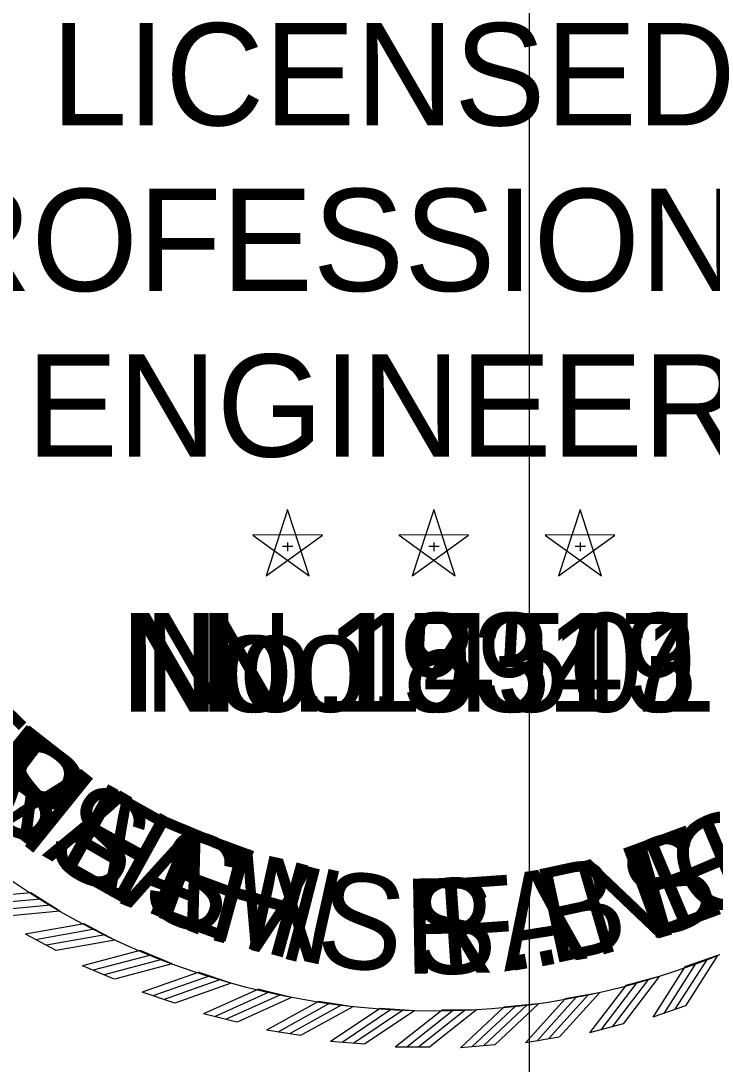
# Model space of a CAD drawing. Extents: x 18 to 14744716, y -5 to 1829144.
# Drawn here: x 17.7213 to 17.7969, y 10.8183 to 10.9324 of the extents above; entities that cross this region are included whole.
import ezdxf

# ---------------------------------------------------------------- set-up
doc = ezdxf.new("R2010")
doc.units = 0
for name, color, linetype in [('B_StampHSS', 7, 'Continuous'), ('B_StampJSB', 7, 'Continuous'), ('B_StampSCR', 7, 'Continuous'), ('B_StampSFH', 7, 'Continuous'), ('R_No Plot', 7, 'Continuous')]:
    doc.layers.add(name, color=color, linetype=linetype)

msp = doc.modelspace()

# ---------------------------------------------------------------- linework, layer by layer
at = {"layer": 'B_StampHSS'}
for p, q in [((17.75045, 10.87892), (17.74809, 10.87168)), ((17.7528, 10.87168), (17.75045, 10.87893)), ((17.76644, 10.87892), (17.76408, 10.87168)), ((17.76879, 10.87168), (17.76644, 10.87893)), ((17.78243, 10.87892), (17.78007, 10.87168)), ((17.78478, 10.87168), (17.78243, 10.87893)), ((17.75425, 10.87615), (17.74664, 10.87616)), ((17.74664, 10.87615), (17.7528, 10.87168)), ((17.7481, 10.87168), (17.75426, 10.87615)), ((17.75045, 10.87534), (17.75045, 10.87439)), ((17.77024, 10.87615), (17.76263, 10.87616)), ((17.76264, 10.87615), (17.76879, 10.87168)), ((17.76409, 10.87168), (17.77025, 10.87615)), ((17.76645, 10.87534), (17.76645, 10.87439)), ((17.78623, 10.87615), (17.77862, 10.87616)), ((17.77863, 10.87615), (17.78478, 10.87168)), ((17.78008, 10.87168), (17.78624, 10.87615)), ((17.78244, 10.87534), (17.78244, 10.87439)), ((17.7499, 10.87494), (17.75104, 10.87494)), ((17.7659, 10.87494), (17.76703, 10.87494)), ((17.78189, 10.87494), (17.78302, 10.87494)), ((17.72555, 10.83498), (17.72236, 10.83702)), ((17.73156, 10.83184), (17.72822, 10.83361)), ((17.72514, 10.8307), (17.7218, 10.83247)), ((17.73781, 10.82922), (17.73434, 10.8307)), ((17.79746, 10.83015), (17.7939, 10.82889)), ((17.7315, 10.82755), (17.72804, 10.82903)), ((17.74426, 10.82711), (17.74068, 10.82831)), ((17.79108, 10.82784), (17.78743, 10.82688)), ((17.73811, 10.82493), (17.73453, 10.82613)), ((17.75086, 10.82555), (17.74719, 10.82645)), ((17.78453, 10.82608), (17.78081, 10.82542)), ((17.75757, 10.82454), (17.75383, 10.82513)), ((17.77786, 10.82486), (17.7741, 10.82451)), ((17.74491, 10.82287), (17.74125, 10.82376)), ((17.76433, 10.82409), (17.76056, 10.82436)), ((17.77111, 10.82419), (17.76734, 10.82416)), ((17.79395, 10.82465), (17.79039, 10.82339)), ((17.78713, 10.82266), (17.78348, 10.8217)), ((17.75186, 10.82138), (17.74814, 10.82196)), ((17.75891, 10.82046), (17.75515, 10.82074)), ((17.77311, 10.82039), (17.76935, 10.82004)), ((17.78016, 10.82123), (17.77645, 10.82058)), ((17.76601, 10.82013), (17.76224, 10.8201))]:
    msp.add_line(p, q, dxfattribs=at)
for points in [[(17.72237, 10.83701), (17.71587, 10.83641)], [(17.72342, 10.83632), (17.71692, 10.83572)], [(17.72454, 10.83564), (17.71804, 10.83504)], [(17.72555, 10.83498), (17.71906, 10.83437)], [(17.72822, 10.83361), (17.7218, 10.83247)], [(17.72933, 10.83301), (17.7229, 10.83187)], [(17.7305, 10.83242), (17.72408, 10.83128)], [(17.73157, 10.83184), (17.72514, 10.83071)], [(17.73434, 10.8307), (17.72803, 10.82903)], [(17.73549, 10.83019), (17.72918, 10.82853)], [(17.73671, 10.82971), (17.7304, 10.82804)], [(17.79632, 10.82976), (17.7928, 10.82426)], [(17.79746, 10.83015), (17.79395, 10.82465)], [(17.73782, 10.82922), (17.73151, 10.82755)], [(17.74068, 10.8283), (17.73453, 10.82612)], [(17.7939, 10.82889), (17.79039, 10.82339)], [(17.79509, 10.82929), (17.79158, 10.8238)], [(17.74187, 10.8279), (17.73572, 10.82572)], [(17.74312, 10.82751), (17.73697, 10.82533)], [(17.74427, 10.82712), (17.73812, 10.82494)], [(17.78865, 10.82719), (17.7847, 10.822)], [(17.78991, 10.82755), (17.78596, 10.82236)], [(17.79109, 10.82785), (17.78713, 10.82266)], [(17.74719, 10.82644), (17.74125, 10.82376)], [(17.74841, 10.82613), (17.74246, 10.82345)], [(17.78454, 10.82608), (17.78017, 10.82124)], [(17.78743, 10.82688), (17.78348, 10.82169)], [(17.74969, 10.82585), (17.74374, 10.82317)], [(17.75087, 10.82556), (17.74492, 10.82287)], [(17.75384, 10.82513), (17.74813, 10.82196)], [(17.75508, 10.82492), (17.74937, 10.82176)], [(17.77787, 10.82486), (17.77311, 10.82039)], [(17.78082, 10.82542), (17.77645, 10.82058)], [(17.78206, 10.82563), (17.77769, 10.82078)], [(17.78334, 10.82588), (17.77897, 10.82104)], [(17.75637, 10.82474), (17.75067, 10.82158)], [(17.75757, 10.82454), (17.75187, 10.82138)], [(17.76057, 10.82436), (17.75514, 10.82074)], [(17.76182, 10.82426), (17.7564, 10.82063)], [(17.76313, 10.82419), (17.7577, 10.82057)], [(17.76434, 10.82409), (17.75891, 10.82047)], [(17.76734, 10.82415), (17.76223, 10.8201)], [(17.7686, 10.82415), (17.76349, 10.8201)], [(17.7699, 10.8242), (17.7648, 10.82014)], [(17.77112, 10.8242), (17.76601, 10.82014)], [(17.7741, 10.82451), (17.76935, 10.82004)], [(17.77536, 10.82461), (17.7706, 10.82015)], [(17.77666, 10.82476), (17.7719, 10.82029)]]:
    msp.add_lwpolyline(points, dxfattribs=at)
at = {"layer": 'B_StampJSB'}
for p, q in [((17.75045, 10.87892), (17.74809, 10.87168)), ((17.7528, 10.87168), (17.75045, 10.87893)), ((17.76644, 10.87892), (17.76408, 10.87168)), ((17.76879, 10.87168), (17.76644, 10.87893)), ((17.78243, 10.87892), (17.78007, 10.87168)), ((17.78478, 10.87168), (17.78243, 10.87893)), ((17.75425, 10.87615), (17.74664, 10.87616)), ((17.74664, 10.87615), (17.7528, 10.87168)), ((17.7481, 10.87168), (17.75426, 10.87615)), ((17.75045, 10.87534), (17.75045, 10.87439)), ((17.77024, 10.87615), (17.76263, 10.87616)), ((17.76264, 10.87615), (17.76879, 10.87168)), ((17.76409, 10.87168), (17.77025, 10.87615)), ((17.76645, 10.87534), (17.76645, 10.87439)), ((17.78623, 10.87615), (17.77862, 10.87616)), ((17.77863, 10.87615), (17.78478, 10.87168)), ((17.78008, 10.87168), (17.78624, 10.87615)), ((17.78244, 10.87534), (17.78244, 10.87439)), ((17.7499, 10.87494), (17.75104, 10.87494)), ((17.7659, 10.87494), (17.76703, 10.87494)), ((17.78189, 10.87494), (17.78302, 10.87494)), ((17.72555, 10.83498), (17.72236, 10.83702)), ((17.73156, 10.83184), (17.72822, 10.83361)), ((17.72514, 10.8307), (17.7218, 10.83247)), ((17.73781, 10.82922), (17.73434, 10.8307)), ((17.79746, 10.83015), (17.7939, 10.82889)), ((17.7315, 10.82755), (17.72804, 10.82903)), ((17.74426, 10.82711), (17.74068, 10.82831)), ((17.79108, 10.82784), (17.78743, 10.82688)), ((17.73811, 10.82493), (17.73453, 10.82613)), ((17.75086, 10.82555), (17.74719, 10.82645)), ((17.78453, 10.82608), (17.78081, 10.82542)), ((17.75757, 10.82454), (17.75383, 10.82513)), ((17.77786, 10.82486), (17.7741, 10.82451)), ((17.74491, 10.82287), (17.74125, 10.82376)), ((17.76433, 10.82409), (17.76056, 10.82436)), ((17.77111, 10.82419), (17.76734, 10.82416)), ((17.79395, 10.82465), (17.79039, 10.82339)), ((17.78713, 10.82266), (17.78348, 10.8217)), ((17.75186, 10.82138), (17.74814, 10.82196)), ((17.75891, 10.82046), (17.75515, 10.82074)), ((17.77311, 10.82039), (17.76935, 10.82004)), ((17.78016, 10.82123), (17.77645, 10.82058)), ((17.76601, 10.82013), (17.76224, 10.8201))]:
    msp.add_line(p, q, dxfattribs=at)
for points in [[(17.72237, 10.83701), (17.71587, 10.83641)], [(17.72342, 10.83632), (17.71692, 10.83572)], [(17.72454, 10.83564), (17.71804, 10.83504)], [(17.72555, 10.83498), (17.71906, 10.83437)], [(17.72822, 10.83361), (17.7218, 10.83247)], [(17.72933, 10.83301), (17.7229, 10.83187)], [(17.7305, 10.83242), (17.72408, 10.83128)], [(17.73157, 10.83184), (17.72514, 10.83071)], [(17.73434, 10.8307), (17.72803, 10.82903)], [(17.73549, 10.83019), (17.72918, 10.82853)], [(17.73671, 10.82971), (17.7304, 10.82804)], [(17.79632, 10.82976), (17.7928, 10.82426)], [(17.79746, 10.83015), (17.79395, 10.82465)], [(17.73782, 10.82922), (17.73151, 10.82755)], [(17.74068, 10.8283), (17.73453, 10.82612)], [(17.7939, 10.82889), (17.79039, 10.82339)], [(17.79509, 10.82929), (17.79158, 10.8238)], [(17.74187, 10.8279), (17.73572, 10.82572)], [(17.74312, 10.82751), (17.73697, 10.82533)], [(17.74427, 10.82712), (17.73812, 10.82494)], [(17.78865, 10.82719), (17.7847, 10.822)], [(17.78991, 10.82755), (17.78596, 10.82236)], [(17.79109, 10.82785), (17.78713, 10.82266)], [(17.74719, 10.82644), (17.74125, 10.82376)], [(17.74841, 10.82613), (17.74246, 10.82345)], [(17.78454, 10.82608), (17.78017, 10.82124)], [(17.78743, 10.82688), (17.78348, 10.82169)], [(17.74969, 10.82585), (17.74374, 10.82317)], [(17.75087, 10.82556), (17.74492, 10.82287)], [(17.75384, 10.82513), (17.74813, 10.82196)], [(17.75508, 10.82492), (17.74937, 10.82176)], [(17.77787, 10.82486), (17.77311, 10.82039)], [(17.78082, 10.82542), (17.77645, 10.82058)], [(17.78206, 10.82563), (17.77769, 10.82078)], [(17.78334, 10.82588), (17.77897, 10.82104)], [(17.75637, 10.82474), (17.75067, 10.82158)], [(17.75757, 10.82454), (17.75187, 10.82138)], [(17.76057, 10.82436), (17.75514, 10.82074)], [(17.76182, 10.82426), (17.7564, 10.82063)], [(17.76313, 10.82419), (17.7577, 10.82057)], [(17.76434, 10.82409), (17.75891, 10.82047)], [(17.76734, 10.82415), (17.76223, 10.8201)], [(17.7686, 10.82415), (17.76349, 10.8201)], [(17.7699, 10.8242), (17.7648, 10.82014)], [(17.77112, 10.8242), (17.76601, 10.82014)], [(17.7741, 10.82451), (17.76935, 10.82004)], [(17.77536, 10.82461), (17.7706, 10.82015)], [(17.77666, 10.82476), (17.7719, 10.82029)]]:
    msp.add_lwpolyline(points, dxfattribs=at)
msp.add_circle((17.76645, 10.90612), 0.08205, dxfattribs=at)
at = {"layer": 'B_StampSCR'}
for p, q in [((17.75045, 10.87892), (17.74809, 10.87168)), ((17.7528, 10.87168), (17.75045, 10.87893)), ((17.76644, 10.87892), (17.76408, 10.87168)), ((17.76879, 10.87168), (17.76644, 10.87893)), ((17.78243, 10.87892), (17.78007, 10.87168)), ((17.78478, 10.87168), (17.78243, 10.87893)), ((17.75425, 10.87615), (17.74664, 10.87616)), ((17.74664, 10.87615), (17.7528, 10.87168)), ((17.7481, 10.87168), (17.75426, 10.87615)), ((17.75045, 10.87534), (17.75045, 10.87439)), ((17.77024, 10.87615), (17.76263, 10.87616)), ((17.76264, 10.87615), (17.76879, 10.87168)), ((17.76409, 10.87168), (17.77025, 10.87615)), ((17.76645, 10.87534), (17.76645, 10.87439)), ((17.78623, 10.87615), (17.77862, 10.87616)), ((17.77863, 10.87615), (17.78478, 10.87168)), ((17.78008, 10.87168), (17.78624, 10.87615)), ((17.78244, 10.87534), (17.78244, 10.87439)), ((17.7499, 10.87494), (17.75104, 10.87494)), ((17.7659, 10.87494), (17.76703, 10.87494)), ((17.78189, 10.87494), (17.78302, 10.87494)), ((17.72555, 10.83498), (17.72236, 10.83702)), ((17.73156, 10.83184), (17.72822, 10.83361)), ((17.72514, 10.8307), (17.7218, 10.83247)), ((17.73781, 10.82922), (17.73434, 10.8307)), ((17.79746, 10.83015), (17.7939, 10.82889)), ((17.7315, 10.82755), (17.72804, 10.82903)), ((17.74426, 10.82711), (17.74068, 10.82831)), ((17.79108, 10.82784), (17.78743, 10.82688)), ((17.73811, 10.82493), (17.73453, 10.82613)), ((17.75086, 10.82555), (17.74719, 10.82645)), ((17.78453, 10.82608), (17.78081, 10.82542)), ((17.75757, 10.82454), (17.75383, 10.82513)), ((17.77786, 10.82486), (17.7741, 10.82451)), ((17.74491, 10.82287), (17.74125, 10.82376)), ((17.76433, 10.82409), (17.76056, 10.82436)), ((17.77111, 10.82419), (17.76734, 10.82416)), ((17.79395, 10.82465), (17.79039, 10.82339)), ((17.78713, 10.82266), (17.78348, 10.8217)), ((17.75186, 10.82138), (17.74814, 10.82196)), ((17.75891, 10.82046), (17.75515, 10.82074)), ((17.77311, 10.82039), (17.76935, 10.82004)), ((17.78016, 10.82123), (17.77645, 10.82058)), ((17.76601, 10.82013), (17.76224, 10.8201))]:
    msp.add_line(p, q, dxfattribs=at)
for points in [[(17.72237, 10.83701), (17.71587, 10.83641)], [(17.72342, 10.83632), (17.71692, 10.83572)], [(17.72454, 10.83564), (17.71804, 10.83504)], [(17.72555, 10.83498), (17.71906, 10.83437)], [(17.72822, 10.83361), (17.7218, 10.83247)], [(17.72933, 10.83301), (17.7229, 10.83187)], [(17.7305, 10.83242), (17.72408, 10.83128)], [(17.73157, 10.83184), (17.72514, 10.83071)], [(17.73434, 10.8307), (17.72803, 10.82903)], [(17.73549, 10.83019), (17.72918, 10.82853)], [(17.73671, 10.82971), (17.7304, 10.82804)], [(17.79632, 10.82976), (17.7928, 10.82426)], [(17.79746, 10.83015), (17.79395, 10.82465)], [(17.73782, 10.82922), (17.73151, 10.82755)], [(17.74068, 10.8283), (17.73453, 10.82612)], [(17.7939, 10.82889), (17.79039, 10.82339)], [(17.79509, 10.82929), (17.79158, 10.8238)], [(17.74187, 10.8279), (17.73572, 10.82572)], [(17.74312, 10.82751), (17.73697, 10.82533)], [(17.74427, 10.82712), (17.73812, 10.82494)], [(17.78865, 10.82719), (17.7847, 10.822)], [(17.78991, 10.82755), (17.78596, 10.82236)], [(17.79109, 10.82785), (17.78713, 10.82266)], [(17.74719, 10.82644), (17.74125, 10.82376)], [(17.74841, 10.82613), (17.74246, 10.82345)], [(17.78454, 10.82608), (17.78017, 10.82124)], [(17.78743, 10.82688), (17.78348, 10.82169)], [(17.74969, 10.82585), (17.74374, 10.82317)], [(17.75087, 10.82556), (17.74492, 10.82287)], [(17.75384, 10.82513), (17.74813, 10.82196)], [(17.75508, 10.82492), (17.74937, 10.82176)], [(17.77787, 10.82486), (17.77311, 10.82039)], [(17.78082, 10.82542), (17.77645, 10.82058)], [(17.78206, 10.82563), (17.77769, 10.82078)], [(17.78334, 10.82588), (17.77897, 10.82104)], [(17.75637, 10.82474), (17.75067, 10.82158)], [(17.75757, 10.82454), (17.75187, 10.82138)], [(17.76057, 10.82436), (17.75514, 10.82074)], [(17.76182, 10.82426), (17.7564, 10.82063)], [(17.76313, 10.82419), (17.7577, 10.82057)], [(17.76434, 10.82409), (17.75891, 10.82047)], [(17.76734, 10.82415), (17.76223, 10.8201)], [(17.7686, 10.82415), (17.76349, 10.8201)], [(17.7699, 10.8242), (17.7648, 10.82014)], [(17.77112, 10.8242), (17.76601, 10.82014)], [(17.7741, 10.82451), (17.76935, 10.82004)], [(17.77536, 10.82461), (17.7706, 10.82015)], [(17.77666, 10.82476), (17.7719, 10.82029)]]:
    msp.add_lwpolyline(points, dxfattribs=at)
at = {"layer": 'B_StampSFH'}
for p, q in [((17.75045, 10.87892), (17.74809, 10.87168)), ((17.7528, 10.87168), (17.75045, 10.87893)), ((17.76644, 10.87892), (17.76408, 10.87168)), ((17.76879, 10.87168), (17.76644, 10.87893)), ((17.78243, 10.87892), (17.78007, 10.87168)), ((17.78478, 10.87168), (17.78243, 10.87893)), ((17.75425, 10.87615), (17.74664, 10.87616)), ((17.74664, 10.87615), (17.7528, 10.87168)), ((17.7481, 10.87168), (17.75426, 10.87615)), ((17.75045, 10.87534), (17.75045, 10.87439)), ((17.77024, 10.87615), (17.76263, 10.87616)), ((17.76264, 10.87615), (17.76879, 10.87168)), ((17.76409, 10.87168), (17.77025, 10.87615)), ((17.76645, 10.87534), (17.76645, 10.87439)), ((17.78623, 10.87615), (17.77862, 10.87616)), ((17.77863, 10.87615), (17.78478, 10.87168)), ((17.78008, 10.87168), (17.78624, 10.87615)), ((17.78244, 10.87534), (17.78244, 10.87439)), ((17.7499, 10.87494), (17.75104, 10.87494)), ((17.7659, 10.87494), (17.76703, 10.87494)), ((17.78189, 10.87494), (17.78302, 10.87494)), ((17.72555, 10.83498), (17.72236, 10.83702)), ((17.73156, 10.83184), (17.72822, 10.83361)), ((17.72514, 10.8307), (17.7218, 10.83247)), ((17.73781, 10.82922), (17.73434, 10.8307)), ((17.79746, 10.83015), (17.7939, 10.82889)), ((17.7315, 10.82755), (17.72804, 10.82903)), ((17.74426, 10.82711), (17.74068, 10.82831)), ((17.79108, 10.82784), (17.78743, 10.82688)), ((17.73811, 10.82493), (17.73453, 10.82613)), ((17.75086, 10.82555), (17.74719, 10.82645)), ((17.78453, 10.82608), (17.78081, 10.82542)), ((17.75757, 10.82454), (17.75383, 10.82513)), ((17.77786, 10.82486), (17.7741, 10.82451)), ((17.74491, 10.82287), (17.74125, 10.82376)), ((17.76433, 10.82409), (17.76056, 10.82436)), ((17.77111, 10.82419), (17.76734, 10.82416)), ((17.79395, 10.82465), (17.79039, 10.82339)), ((17.78713, 10.82266), (17.78348, 10.8217)), ((17.75186, 10.82138), (17.74814, 10.82196)), ((17.75891, 10.82046), (17.75515, 10.82074)), ((17.77311, 10.82039), (17.76935, 10.82004)), ((17.78016, 10.82123), (17.77645, 10.82058)), ((17.76601, 10.82013), (17.76224, 10.8201))]:
    msp.add_line(p, q, dxfattribs=at)
for points in [[(17.72237, 10.83701), (17.71587, 10.83641)], [(17.72342, 10.83632), (17.71692, 10.83572)], [(17.72454, 10.83564), (17.71804, 10.83504)], [(17.72555, 10.83498), (17.71906, 10.83437)], [(17.72822, 10.83361), (17.7218, 10.83247)], [(17.72933, 10.83301), (17.7229, 10.83187)], [(17.7305, 10.83242), (17.72408, 10.83128)], [(17.73157, 10.83184), (17.72514, 10.83071)], [(17.73434, 10.8307), (17.72803, 10.82903)], [(17.73549, 10.83019), (17.72918, 10.82853)], [(17.73671, 10.82971), (17.7304, 10.82804)], [(17.79632, 10.82976), (17.7928, 10.82426)], [(17.79746, 10.83015), (17.79395, 10.82465)], [(17.73782, 10.82922), (17.73151, 10.82755)], [(17.74068, 10.8283), (17.73453, 10.82612)], [(17.7939, 10.82889), (17.79039, 10.82339)], [(17.79509, 10.82929), (17.79158, 10.8238)], [(17.74187, 10.8279), (17.73572, 10.82572)], [(17.74312, 10.82751), (17.73697, 10.82533)], [(17.74427, 10.82712), (17.73812, 10.82494)], [(17.78865, 10.82719), (17.7847, 10.822)], [(17.78991, 10.82755), (17.78596, 10.82236)], [(17.79109, 10.82785), (17.78713, 10.82266)], [(17.74719, 10.82644), (17.74125, 10.82376)], [(17.74841, 10.82613), (17.74246, 10.82345)], [(17.78454, 10.82608), (17.78017, 10.82124)], [(17.78743, 10.82688), (17.78348, 10.82169)], [(17.74969, 10.82585), (17.74374, 10.82317)], [(17.75087, 10.82556), (17.74492, 10.82287)], [(17.75384, 10.82513), (17.74813, 10.82196)], [(17.75508, 10.82492), (17.74937, 10.82176)], [(17.77787, 10.82486), (17.77311, 10.82039)], [(17.78082, 10.82542), (17.77645, 10.82058)], [(17.78206, 10.82563), (17.77769, 10.82078)], [(17.78334, 10.82588), (17.77897, 10.82104)], [(17.75637, 10.82474), (17.75067, 10.82158)], [(17.75757, 10.82454), (17.75187, 10.82138)], [(17.76057, 10.82436), (17.75514, 10.82074)], [(17.76182, 10.82426), (17.7564, 10.82063)], [(17.76313, 10.82419), (17.7577, 10.82057)], [(17.76434, 10.82409), (17.75891, 10.82047)], [(17.76734, 10.82415), (17.76223, 10.8201)], [(17.7686, 10.82415), (17.76349, 10.8201)], [(17.7699, 10.8242), (17.7648, 10.82014)], [(17.77112, 10.8242), (17.76601, 10.82014)], [(17.7741, 10.82451), (17.76935, 10.82004)], [(17.77536, 10.82461), (17.7706, 10.82015)], [(17.77666, 10.82476), (17.7719, 10.82029)]]:
    msp.add_lwpolyline(points, dxfattribs=at)
at = {"layer": 'R_No Plot'}
msp.add_lwpolyline([(17.77692, 16.62761), (51.77692, 16.62761), (51.77692, -5.37239), (17.77692, -5.37239)], close=True, dxfattribs=at)

# ---------------------------------------------------------------- texts
at = {"layer": 'B_StampHSS'}
for s, height, p in [('LICENSED', 0.011194, (17.72458, 10.92096)), ('PROFESSIONAL', 0.0111938, (17.70165, 10.90284)), ('ENGINEER', 0.011194, (17.72191, 10.88472)), ('No.18919', 0.010794, (17.73257, 10.85681))]:
    msp.add_text(s, height=height, dxfattribs=at).set_placement(p)
for s, rotation, p in [('S', 323.717, (17.71548, 10.84678)), ('S', 331.0048, (17.72342, 10.8408)), ('A', 338.2926, (17.73206, 10.83587)), ('S', 21.655, (17.78968, 10.83144)), ('M', 345.5804, (17.74125, 10.83208)), ('S', 2.7067, (17.76417, 10.82794)), ('.', 9.9945, (17.77411, 10.82829))]:
    msp.add_text(s, height=0.01042, rotation=rotation, dxfattribs=at).set_placement(p)
at = {"layer": 'B_StampJSB'}
for s, height, p in [('LICENSED', 0.011194, (17.72458, 10.92096)), ('PROFESSIONAL', 0.0111938, (17.70165, 10.90284)), ('ENGINEER', 0.011194, (17.72191, 10.88472)), ('No.5343 ', 0.010794, (17.74071, 10.85681))]:
    msp.add_text(s, height=height, dxfattribs=at).set_placement(p)
for s, rotation, p in [('M', 321.1392, (17.71449, 10.84796)), ('E', 330.6263, (17.72478, 10.84019)), ('E', 20.2514, (17.78968, 10.83167)), ('S', 338.289, (17.73395, 10.83522)), ('B', 12.2238, (17.77906, 10.82915)), ('S', 353.2495, (17.75335, 10.82924)), ('.', 0.5473, (17.76322, 10.82819))]:
    msp.add_text(s, height=0.01042, rotation=rotation, dxfattribs=at).set_placement(p)
at = {"layer": 'B_StampSCR'}
for s, height, p in [('LICENSED', 0.011194, (17.72458, 10.92096)), ('PROFESSIONAL', 0.0111938, (17.70165, 10.90284)), ('ENGINEER', 0.011194, (17.72191, 10.88472)), ('No.19317', 0.010794, (17.73214, 10.85681))]:
    msp.add_text(s, height=height, dxfattribs=at).set_placement(p)
for s, rotation, p in [('R', 321.9569, (17.71489, 10.84781)), ('A', 329.9825, (17.72354, 10.84113)), ('T', 337.2785, (17.73214, 10.83616)), ('G', 25.0674, (17.79533, 10.83343)), ('H', 344.5745, (17.74131, 10.83232)), ('N', 16.3122, (17.78393, 10.82994)), ('R', 0.9905, (17.7632, 10.82812)), ('A', 9.0162, (17.77412, 10.82838))]:
    msp.add_text(s, height=0.01042, rotation=rotation, dxfattribs=at).set_placement(p)
at = {"layer": 'B_StampSFH'}
for s, height, p in [('LICENSED', 0.011194, (17.72458, 10.92096)), ('PROFESSIONAL', 0.0111938, (17.70165, 10.90284)), ('ENGINEER', 0.011194, (17.72191, 10.88472)), ('No.14501', 0.010794, (17.73471, 10.85681))]:
    msp.add_text(s, height=height, dxfattribs=at).set_placement(p)
for s, rotation, p in [('E', 315.3905, (17.70857, 10.85413)), ('P', 323.0513, (17.71602, 10.84682)), ('H', 331.0769, (17.72479, 10.84031)), ('H', 22.8786, (17.79253, 10.8324)), ('E', 339.8321, (17.73529, 10.83468)), ('N', 347.4929, (17.7451, 10.83112)), ('F', 3.9089, (17.76717, 10.82804)), ('.', 11.205, (17.77708, 10.82872))]:
    msp.add_text(s, height=0.01042, rotation=rotation, dxfattribs=at).set_placement(p)

doc.saveas('drawing.dxf')
